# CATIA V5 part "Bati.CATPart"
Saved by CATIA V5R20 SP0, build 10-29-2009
Part number: Bâti
Bounding box of the stored display mesh (mm): x 0 to 30, y -188 to 120, z -44.983 to 474.894
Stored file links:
  D:\thinkmotion-MPB\Dropbox\IAO_2011\MMS_GR3\aweinling\aweinling\Bati.CATPart
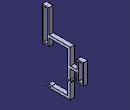
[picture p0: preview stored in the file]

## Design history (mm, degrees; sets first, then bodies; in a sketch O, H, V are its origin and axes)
Parameters
  D_Trou = 10 mm
  D_Pivot = 30 mm
Body1 (main body)
  Sketch1 on yz-plane, origin (0, 0, 0), H (0, 1, 0), V (0, 0, 1)
    line L1 (-130, -40) -> (21, -40)
    line L2 (21, -40) -> (21, 160)
    line L3 (21, 160) -> (70, 160)
    line L4 (-130, -40) -> (-130, -20)
    line L5 (-130, -20) -> (1, -20)
    line L6 (1, -20) -> (1, 280)
    line L7 (1, 280) -> (-138, 280)
    line L8 (-138, 300) -> (21, 300)
    point P10 (21, 300)
    line L9 (21, 300) -> (21, 180)
    line L10 (21, 180) -> (70, 180)
    line L11 (70, 160) -> (70, 180)
    line L12 (-138, 280) -> (-138, 300)
    length L1 = 151
    length L2 = 200
    length L3 = 49
    length L4 = 20
    length L6 = 300
    distance L6 L2 = 20
    length L7 = 139
    distance L8 L7 = 20
    distance L10 L3 = 20
    horizontal: L1 H, L3 H, L5 H, L7 H, L8 H, L10 H
    vertical: L2 V, L4 V, L6 V, L9 V, L11 V, L12 V
    coincidence: P10 L2
  Pad1: profile Sketch1, direction (1, 0, 0), length 30
  Sketch2 on yz-plane, origin (0, 0, 0), H (0, 1, 0), V (0, 0, 1)
    line L1 (70, 248.73) -> (120, 248.73)
    line L2 (120, 248.73) -> (120, 98.73)
    line L3 (120, 98.73) -> (70, 98.73)
    line L4 (70, 98.73) -> (70, 248.73)
    line L5 (-188, 474.8942) -> (-138, 474.8942)
    line L6 (-138, 474.8942) -> (-138, 224.8942)
    line L7 (-138, 224.8942) -> (-188, 224.8942)
    line L8 (-188, 224.8942) -> (-188, 474.8942)
    reference projected line E1 (-138, 300) -> (-138, 280) from edge [face of Pad1 from Sketch1.L12 | end face of Pad1]
    reference projected line E2 (70, 160) -> (70, 180) from edge [face of Pad1 from Sketch1.L11 | end face of Pad1]
    length L4 = 150
    length L1 = 50
    length L6 = 250
    length L7 = 50
    horizontal: L1 H, L3 H, L5 H, L7 H
    vertical: L2 V, L4 V, L6 V, L8 V
    coincidence: L6 E1, L4 E2
  Pad2: profile Sketch2, direction (1, 0, 0), length 30
  Sketch3 on yz-plane, origin (0, 0, 0), H (0, 1, 0), V (0, 0, 1)
    line L1 (-178, 464.8942) -> (-148, 464.8942)
    line L2 (-148, 464.8942) -> (-148, 234.8942)
    line L3 (-148, 234.8942) -> (-178, 234.8942)
    line L4 (-178, 234.8942) -> (-178, 464.8942)
    reference projected line E1 (-188, 224.8942) -> (-138, 224.8942) from edge [face of Pad2 from Sketch2.L7 | end face of Pad2]
    reference projected line E2 (-188, 474.8942) -> (-188, 224.8942) from edge [face of Pad2 from Sketch2.L8 | end face of Pad2]
    length L4 = 230
    length L3 = 30
    distance L3 E1 = 10
    distance L4 E2 = 10
    horizontal: L1 H, L3 H
    vertical: L2 V, L4 V
  Pocket1: profile Sketch3, direction (1, 0, 0), length 30
  Sketch4 on yz-plane, origin (0, 0, 0), H (0, 1, 0), V (0, 0, 1)
    line L1 (80, 238.73) -> (110, 238.73)
    line L2 (110, 238.73) -> (110, 108.73)
    line L3 (110, 108.73) -> (80, 108.73)
    line L4 (80, 108.73) -> (80, 238.73)
    reference projected line E1 (70, 98.73) -> (120, 98.73) from edge [face of Pad2 from Sketch2.L3 | end face of Pad2]
    reference projected line E2 (120, 98.73) -> (120, 248.73) from edge [face of Pad2 from Sketch2.L2 | end face of Pad2]
    length L2 = 130
    length L3 = 30
    distance L3 E1 = 10
    distance L2 E2 = 10
    horizontal: L1 H, L3 H
    vertical: L2 V, L4 V
  Pocket2: profile Sketch4, direction (1, 0, 0), length 30
  Sketch5 on yz-plane, origin (0, 0, 0), H (0, 1, 0), V (0, 0, 1)
    circle A1 centre (-130, -30) radius 15
    radius A1 = 15 {= D_Pivot /2}
  Pad3: profile Sketch5, direction (1, 0, 0), length 30
  Sketch6 on face of Pad3, origin (30, -132.7014, -30.7409), H (0, 1, 0), V (0, 0, 1)
    point P1 (2.7014, 0.7409)
    reference projected circle E1 centre (2.7014, 0.7409) radius 15 from edge [face of Pad3 from Sketch5.A1 | face of Pad3]
    concentricity: P1 E1
  Hole1: placed by Sketch6, at (30, -130, -30) direction (-1, 0, 0), diameter 10 {= D_Trou}, through (limit type 3)
  Sketch7 on yz-plane, origin (0, 0, 0), H (0, 1, 0), V (0, 0, 1)
    circle A1 centre (11, 81) radius 15
    point P1 (11, 81)
    reference projected line E1 (-130, -40) -> (21, -40) from edge [face of Pad1 from Sketch1.L1 | face of Pad3]
    reference projected line E2 (1, 280) -> (1, -20) from edge [face of Pad1 from Sketch1.L6 | end face of Pad1]
    distance P1 E1 = 121
    distance P1 E2 = 10
    radius A1 = 15 {= D_Pivot /2}
  Pad4: profile Sketch7, direction (1, 0, 0), length 30
  Sketch8 on face of Pad4, origin (30, 14.8501, 81), H (0, 1, 0), V (0, 0, 1)
    point P1 (-3.8501, 0)
    reference projected arc E1 centre (-3.8501, 0) radius 15 from (6.1499, -11.1803) to (6.1499, 11.1803) ccw from edge [face of Pad4 from Sketch7.A1 | face of Pad4]
    concentricity: P1 E1
  Hole2: placed by Sketch8, at (30, 11, 81) direction (-1, 0, 0), diameter 10 {= D_Trou}, through (limit type 3)
  Point1: (0, 0, 0), relative to Sketch8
